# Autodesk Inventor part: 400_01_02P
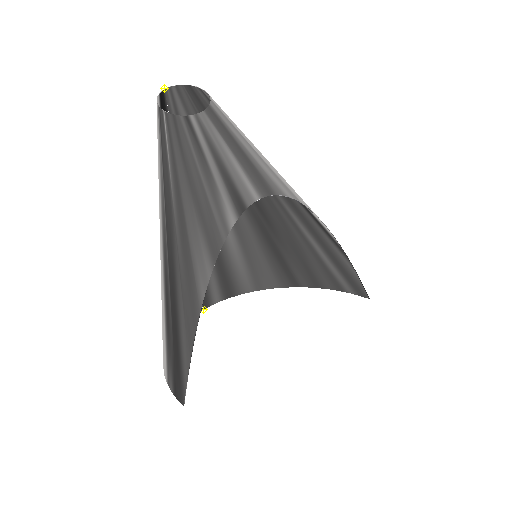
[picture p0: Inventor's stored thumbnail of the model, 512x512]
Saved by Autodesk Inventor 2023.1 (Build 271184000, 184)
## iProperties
Company: Fabian Stasiak CAD Consulting
Category: Autodesk® Inventor® Tutorial Series
Created: 2017-01
Part Number: 400_01_02P
Material: Steel
Document SubType Name: Konstrukcja blachowa
Designer: F.Stasiak
Density: 7.85 g/cm^3
Sheet Metal Rule: Blacha stalowa 1.0 mm/Spoina liniowa
Sheet Metal Width: 0,000 mm
Sheet Metal Length: 0,000 mm
Sheet Metal Area: 0,000 mm^2
Appearance: Semi-Polished
Description: Cone 50x250
Mass: 2205.66 g
Surface Area: 5647.14 cm^2
Volume: 280.975 cm^3
Catalog Web Link: www.expertbooks.eu
FLATAREA: =<FLAT PATTERN AREA>
Thickness: 1,000 mm
Author: F.Stasiak
Subject: Sheet Metal Design. Basic and Advanced techniques
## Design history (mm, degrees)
derived "400_01_W_BASE.ipt"
feature "Pogrubienie1" dims "d1" = 1 (= Thickness), "d2" = 1 (= Thickness)
node "Punkt konstrukcyjny1"
node "Punkt konstrukcyjny2"
feature "Rozdarcie1" dims "d3" = 1 (= GapSize)
node "Bryła1"
body "Srf1"
feature "Srf1::Pochodne"
other parameters: "Thickness" = 1 (derived), "WspółczynnikK" = 4.4, "BendRadius" = 1 (= Thickness), "BendReliefWidth" = 1 (= Thickness), "BendReliefDepth" = 0.5 (= 0.5 x Thickness), "CornerReliefSize" = 4 (= 4 x Thickness), "OdstępPołączenia" = 0.01, "MinimumRemnant" = 2 (= 2 x Thickness), "TransitionRadius" = 1 (= BendRadius), "JacobiRadiusSize" = 1 (= BendRadius), "GapSize" = 1 (= Thickness), "d4" = 1 (= Thickness)
